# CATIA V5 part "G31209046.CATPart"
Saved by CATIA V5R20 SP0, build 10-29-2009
Part number: G31209046
Revision: 6
Definition: design
Nomenclature: G31209046
Source: made
Description: NOT SPECIFIED
Bounding box of the stored display mesh (mm): x -5 to 46, y -8 to 8, z -8 to 8
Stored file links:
  C:\Users\Raffaele\Desktop\3D X SITO CF\BOLEX\23-BUSH REF 312\G31209046.CATPart

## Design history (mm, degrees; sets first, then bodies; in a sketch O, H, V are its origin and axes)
Body1 "MANIFOLD_SOLID_BREP #10239" (main body)
  Solid1: solid without history
Body2 "MANIFOLD_SOLID_BREP #10382"
  Solid2: solid without history
Body3 "MANIFOLD_SOLID_BREP #10525"
  Solid3: solid without history
Body4 "MANIFOLD_SOLID_BREP #10668"
  Solid4: solid without history
Body5 "MANIFOLD_SOLID_BREP #10811"
  Solid5: solid without history
Body6 "MANIFOLD_SOLID_BREP #10956"
  Solid6: solid without history
Body7 "MANIFOLD_SOLID_BREP #11101"
  Solid7: solid without history
Body8 "MANIFOLD_SOLID_BREP #11246"
  Solid8: solid without history
Body9 "MANIFOLD_SOLID_BREP #11391"
  Solid9: solid without history
Body10 "MANIFOLD_SOLID_BREP #11536"
  Solid10: solid without history
Body11 "MANIFOLD_SOLID_BREP #11681"
  Solid11: solid without history
Body12 "MANIFOLD_SOLID_BREP #11826"
  Solid12: solid without history
Body13 "MANIFOLD_SOLID_BREP #11971"
  Solid13: solid without history
Body14 "MANIFOLD_SOLID_BREP #12116"
  Solid14: solid without history
Body15 "MANIFOLD_SOLID_BREP #12261"
  Solid15: solid without history
Body16 "MANIFOLD_SOLID_BREP #12406"
  Solid16: solid without history
Body17 "MANIFOLD_SOLID_BREP #12551"
  Solid17: solid without history
Body18 "MANIFOLD_SOLID_BREP #12697"
  Solid18: solid without history
Body19 "MANIFOLD_SOLID_BREP #12843"
  Solid19: solid without history
Body20 "MANIFOLD_SOLID_BREP #12989"
  Solid20: solid without history
Body21 "MANIFOLD_SOLID_BREP #13135"
  Solid21: solid without history
Body22 "MANIFOLD_SOLID_BREP #13280"
  Solid22: solid without history
Body23 "MANIFOLD_SOLID_BREP #13425"
  Solid23: solid without history
Body24 "MANIFOLD_SOLID_BREP #13570"
  Solid24: solid without history
Body25 "MANIFOLD_SOLID_BREP #13715"
  Solid25: solid without history
Body26 "MANIFOLD_SOLID_BREP #13860"
  Solid26: solid without history
Body27 "MANIFOLD_SOLID_BREP #14005"
  Solid27: solid without history
Body28 "MANIFOLD_SOLID_BREP #14151"
  Solid28: solid without history
Body29 "MANIFOLD_SOLID_BREP #14296"
  Solid29: solid without history
Body30 "MANIFOLD_SOLID_BREP #14441"
  Solid30: solid without history
Body31 "MANIFOLD_SOLID_BREP #14586"
  Solid31: solid without history
Body32 "MANIFOLD_SOLID_BREP #14731"
  Solid32: solid without history
Body33 "MANIFOLD_SOLID_BREP #14876"
  Solid33: solid without history
Body34 "MANIFOLD_SOLID_BREP #15021"
  Solid34: solid without history
Body35 "MANIFOLD_SOLID_BREP #15164"
  Solid35: solid without history
Body36 "MANIFOLD_SOLID_BREP #15307"
  Solid36: solid without history
Body37 "MANIFOLD_SOLID_BREP #15452"
  Solid37: solid without history
Body38 "MANIFOLD_SOLID_BREP #15597"
  Solid38: solid without history
Body39 "MANIFOLD_SOLID_BREP #15742"
  Solid39: solid without history
Body40 "MANIFOLD_SOLID_BREP #15887"
  Solid40: solid without history
Body41 "MANIFOLD_SOLID_BREP #16032"
  Solid41: solid without history
Body42 "MANIFOLD_SOLID_BREP #16177"
  Solid42: solid without history
Body43 "MANIFOLD_SOLID_BREP #16323"
  Solid43: solid without history
Body44 "MANIFOLD_SOLID_BREP #16468"
  Solid44: solid without history
Body45 "MANIFOLD_SOLID_BREP #16613"
  Solid45: solid without history
Body46 "MANIFOLD_SOLID_BREP #16758"
  Solid46: solid without history
Body47 "MANIFOLD_SOLID_BREP #16903"
  Solid47: solid without history
Body48 "MANIFOLD_SOLID_BREP #17048"
  Solid48: solid without history
Body49 "MANIFOLD_SOLID_BREP #17193"
  Solid49: solid without history
Body50 "MANIFOLD_SOLID_BREP #17338"
  Solid50: solid without history
Body51 "MANIFOLD_SOLID_BREP #17483"
  Solid51: solid without history
Body52 "MANIFOLD_SOLID_BREP #17628"
  Solid52: solid without history
Body53 "MANIFOLD_SOLID_BREP #17773"
  Solid53: solid without history
Body54 "MANIFOLD_SOLID_BREP #17918"
  Solid54: solid without history
Body55 "MANIFOLD_SOLID_BREP #18063"
  Solid55: solid without history
Body56 "MANIFOLD_SOLID_BREP #18209"
  Solid56: solid without history
Body57 "MANIFOLD_SOLID_BREP #18352"
  Solid57: solid without history
Body58 "MANIFOLD_SOLID_BREP #18495"
  Solid58: solid without history
Body59 "MANIFOLD_SOLID_BREP #18640"
  Solid59: solid without history
Body60 "MANIFOLD_SOLID_BREP #18785"
  Solid60: solid without history
Body61 "MANIFOLD_SOLID_BREP #18930"
  Solid61: solid without history
Body62 "MANIFOLD_SOLID_BREP #19075"
  Solid62: solid without history
Body63 "MANIFOLD_SOLID_BREP #19220"
  Solid63: solid without history
Body64 "MANIFOLD_SOLID_BREP #19365"
  Solid64: solid without history
Body65 "MANIFOLD_SOLID_BREP #19508"
  Solid65: solid without history
Body66 "MANIFOLD_SOLID_BREP #19651"
  Solid66: solid without history
Body67 "MANIFOLD_SOLID_BREP #19796"
  Solid67: solid without history
Body68 "MANIFOLD_SOLID_BREP #19941"
  Solid68: solid without history
Body69 "MANIFOLD_SOLID_BREP #20086"
  Solid69: solid without history
Body70 "MANIFOLD_SOLID_BREP #20231"
  Solid70: solid without history
Body71 "MANIFOLD_SOLID_BREP #20376"
  Solid71: solid without history
Body72 "MANIFOLD_SOLID_BREP #20521"
  Solid72: solid without history
Body73 "MANIFOLD_SOLID_BREP #20667"
  Solid73: solid without history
